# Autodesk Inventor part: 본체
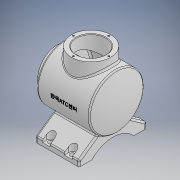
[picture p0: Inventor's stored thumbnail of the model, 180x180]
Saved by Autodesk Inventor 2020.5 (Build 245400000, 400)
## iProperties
Created: 2023-12
Part Number: 본체
Material: 일반
Document SubType Name: Modeling
Designer: 1강의실14
Density: 1 g/cm^3
Appearance: 기본값
Author: 1강의실14
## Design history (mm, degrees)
sketch "스케치1"
  geometry: L1 (-62, 0)-(-62, 36); L2 (-62, 36)-(-50, 36); L3 (-50, 36)-(-50, 50); L4 (-50, 50)-(46.336, 50); L5 (-213.2, 0)-(103.2, 0) reference; L6 (-50, 36)-(-50, 0); A1 r 113 centre (-55, 0) between (58, 0) and (-168, 0); 1 further point
  constraints: 10 end point, 4 perpendicular, 3 point on circle, 3 point on line, 1 centre point, 1 vertical
  dimensions: "d0" = 226 diameter of A1; "d1" = 62 distance from line of point (0, 0) L1; "d2" = 120 distance from line of L1 A1.start; "d3" = 50 distance between parallel lines of L5 L4; "d4" = 36 distance between parallel lines of L5 L2; "d5" = 12 distance between parallel lines of L1 L3; "d6" = 0 distance from line of L5 A1.centre
revolve "회전1" sketch "스케치1" stored, may be unused: angle "d7" = 90 deg
feature "쉘1" dims "d8" = 7
sketch "스케치2"
  geometry: C1 r 50 at (0, 0) reference; C2 r 36 at (0, 0); 1 further point
  constraints: 1 centre point, 1 coincident
  dimensions: "d9" = 72 diameter of C2
extrude "돌출1" join sketch "스케치2" distance "d10" = 12; taper "d11" = 0 deg
sketch "스케치4"
  geometry: L1 (0, -93.179)-(0, 15.53) reference; L2 (-43, -43)-(41.887, -43) reference; L3 (0, -77.65)-(0, -69.806); 3 further points
  constraints: 2 end point, 2 point on line, 1 symmetric about line
sketch "스케치5"
  geometry: L1 (-42.278, -26.694)-(-67, -62); L2 (-67, -62)-(-77, -62); L3 (-77, -62)-(-77, -38.5); L4 (-144.515, 0)-(82.419, 0) reference; L5 (-42.278, 26.694)-(-67, 62); L6 (-67, 62)-(-77, 62); L7 (-77, 62)-(-77, 38.5); L8 (-71.177, 0)-(-60, 0); A1 r 52.096 centre (-112.096, 0) between (-77, -38.5) and (-77, 38.5); 3 further points
  constraints: 14 end point, 3 point on circle, 3 point on line, 3 symmetric about line, 2 perpendicular, 1 centre point, 1 horizontal, 2 other
  dimensions: "d17" = 55 deg angle of L1 L2; "d18" = 10 distance of L1.end L2.end; "d19" = 62 distance from line of L8.start L2; "d20" = 77 distance from line of L3 point (0, 0); "d22" = 77 distance of L7.end L3.end; "d23" = 17 distance from line of L7 L8.end
extrude "돌출2" join sketch "스케치5" stored distance "d24" = 80; taper "d25" = 0 deg
sketch "스케치6"
  geometry: C1 r 36 at (0, 0) reference; 1 further point
hole "구멍1" sketch "스케치6" at (0, 0) diameter "d26" = 54; stored, may be unused: countersink angle "d30" = 90 deg, drill point angle "d32" = 0 deg; dims "d27" = 6, "d28" = 11, "d29" = 6.6, "d31" = 20
node "작업 평면2"
sketch "스케치7"
  geometry: C1 r 36 at (0, 0); 1 further point
  constraints: 1 centre point, 1 coincident
  dimensions: "d34" = 72 diameter of C1
extrude "돌출3" join sketch "스케치7" stored distance "d35" = 10; taper "d36" = 0 deg
sketch "스케치8"
  geometry: C1 r 36 at (0, 0) reference; 1 further point
hole "구멍2" sketch "스케치8" at (0, 0) diameter "d37" = 54; stored, may be unused: countersink angle "d41" = 90 deg, drill point angle "d43" = 0 deg; dims "d38" = 6, "d39" = 11, "d40" = 6.6, "d42" = 50
chamfer "모따기1" distance "d44" = 1; stored, may be unused: second distance "d45" = 2, angle "d46" = 45 deg
sketch "스케치9"
  geometry: L1 (0, 0)-(0, 32.5)
  constraints: 2 end point, 1 vertical
  dimensions: "d47" = 32.5 distance of L1.start L1.end
hole "구멍3" sketch "스케치9" at (0, 32.5) diameter "d48" = 3.242; stored, may be unused: countersink angle "d52" = 90 deg, drill point angle "d54" = 118 deg; dims "d49" = 8, "d50" = 11, "d51" = 6.6, "d53" = 10
fillet "모깎기1" dims "d58" = 3
fillet "모깎기2" dims "d59" = 3
fillet "모깎기3" dims "d60" = 3
sketch "스케치10"
  geometry: L1 (0, 0)-(0, 32.5)
  constraints: 2 end point, 1 vertical
  dimensions: "d61" = 32.5 distance of L1.start L1.end
hole "구멍4" sketch "스케치10" at (0, 32.5) diameter "d62" = 3.242; stored, may be unused: countersink angle "d66" = 90 deg, drill point angle "d68" = 118 deg; dims "d63" = 8, "d64" = 11, "d65" = 6.6, "d67" = 10
node "작업 평면3"
sketch "스케치11"
  geometry: L1 (20, 31.5)-(20, 15.5); L2 (0, 23.5)-(80, 23.5) reference; L3 (13, 31.5)-(13, 15.5); L4 (27, 15.5)-(27, 31.5); L5 (0, 0)-(0, 23.5) reference; L6 (40, -128.3)-(40, 66.3) reference; L7 (53, 15.5)-(53, 31.5); L8 (67, 31.5)-(67, 15.5); A1 r 7 centre (20, 31.5) between (27, 31.5) and (13, 31.5); A2 r 7 centre (20, 15.5) between (13, 15.5) and (27, 15.5); A3 r 7 centre (60, 15.5) between (53, 15.5) and (67, 15.5); A4 r 7 centre (60, 31.5) between (67, 31.5) and (53, 31.5); 6 further points
  constraints: 12 end point, 8 point on circle, 6 symmetric about line, 4 centre point, 4 tangent, 1 midpoint, 1 parallel, 1 perpendicular, 1 point on line, 2 other
  dimensions: "d73" = 20 distance from line of point (20, 23.5) L5; "d74" = 8 distance from line of L2 L1.end; "d76" = 14 distance between parallel lines of L4 L3
extrude "돌출4" cut sketch "스케치11" distance "d77" = 17; taper "d78" = 0 deg
sketch "스케치12"
  geometry: A1 r 7 centre (20, -15.5) between (27, -15.5) and (13, -15.5) reference; A2 r 7 centre (60, -15.5) between (67, -15.5) and (53, -15.5) reference; 1 further point
hole "구멍5" sketch "스케치12" at (20, -15.5), (60, -15.5) diameter "d79" = 9; stored, may be unused: countersink angle "d83" = 90 deg, drill point angle "d85" = 0 deg; dims "d80" = 8, "d81" = 11, "d82" = 6.6, "d84" = 10
node "작업 평면4"
sketch "스케치13"
  geometry: L1 (-62, 36)-(-62, -36) reference; L2 (-80.918, 0)-(65.507, 0) reference; L3 (36, 65)-(36, 50) reference; 2 further points
  constraints: 1 point on line, 1 other
  dimensions: "d87" = 62 distance from line of L1 point (0, 0)
feature "엠보싱1" sketch "스케치13" dims "d88" = 0.5, "d89" = 0
fillet "모깎기4" dims "d90" = 3
fillet "모깎기5" dims "d91" = 3
fillet "모깎기6" dims "d92" = 3
node "솔리드1"
pattern_circular "원형 패턴1" dims angle "d56" = 360 deg
pattern_circular "원형 패턴2" dims angle "d70" = 360 deg
mirror "미러1"
node "투영된 루프1"
node "투영된 루프2"
feature "A9D066F2-1C7D-4E18-AEED-F7BC21143FA4" dims "d26" = 54, "d27" = 6, "d28" = 11, "d29" = 6.6, "d30" = 90 deg, "d31" = 20, "d32" = 0
other parameters: "d33" = 65, "d72" = -6, "d86" = 52.25
